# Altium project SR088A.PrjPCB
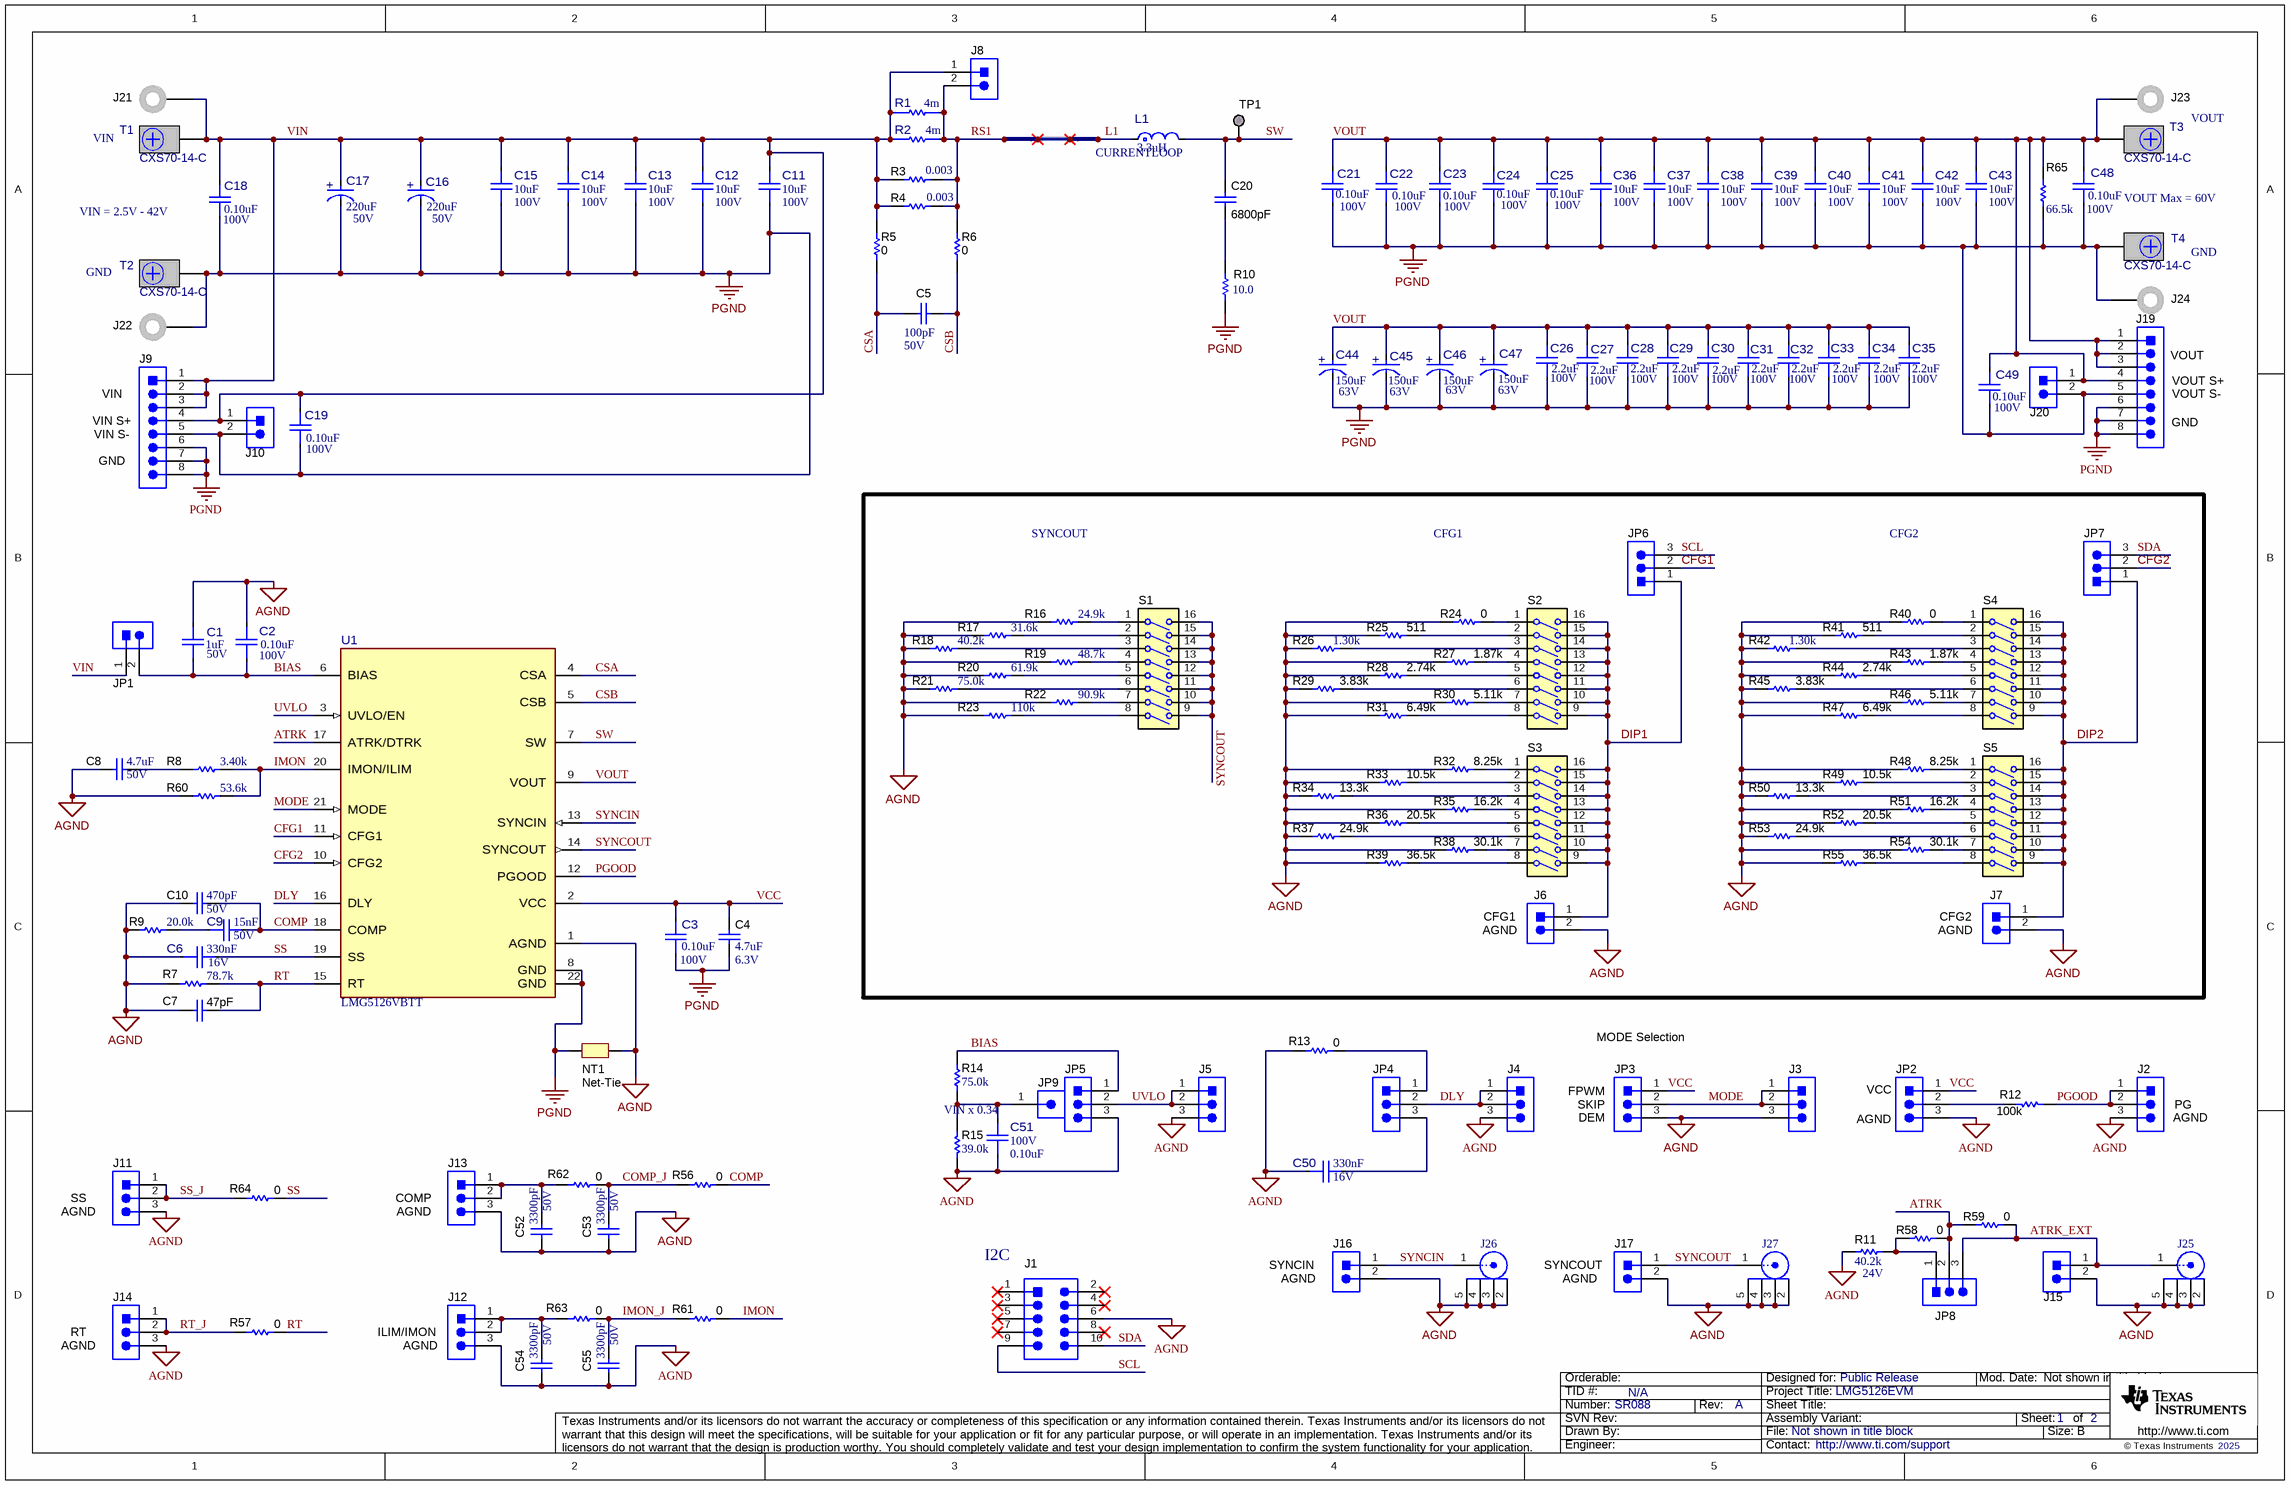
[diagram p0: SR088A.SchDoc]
TID: N/A; TechSupport: http://www.ti.com/support; SCH_Rev: A; PRJ_Title: LMG5126EVM; PRJ_Number: SR088; PRJ_Customer: Public Release; PCB_Rev: A; CopyrightYear: 2025
1 sheet, 168 parts. Net scope: global (net labels, ports and power ports of the same name join across sheets).
Board file: SR088A.PcbDoc

## Sheet SR088A.SchDoc
size 431 x 279 mm; Date: Not shown in title block; ApprovedBy: Not shown in title block; CheckedBy: Not shown in title block; Author: Not shown in title block; CompanyName: Not shown in title block; Engineer: Not shown in title block; Organization: Not shown in title block; Address1: Not shown in title block; Address2: Not shown in title block; Address3: Not shown in title block; Address4: Not shown in title block; DocumentNumber: 1; Revision: Use project parameter SCH_Rev; SheetNumber: 1; SheetTotal: 2; PageSetup: Record=PageOptions¦CenterHorizontal=True¦CenterVertical=True¦PrintScale=1.00¦XCorrection=1.00¦YCorrection=1.00¦PrintKind=0¦BorderSize=5000000¦LeftOffset=0¦BottomOffset=0¦Orientation=2¦PaperLength=1000¦PaperWidth=1000¦Scale=100¦PaperSource=15¦PrintQuality=600¦MediaType=1¦DitherType=10¦PaperKind=Letter¦PrintScaleMode=1

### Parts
C1  ValueDisplayed: 1uF  VDC_V: 50V  [FP-GCM188D71H105KE36J_0603-MFG]  (hidden comment: GCM188D71H105KE36J)
C2  VDC_V: 100V  ValueDisplayed: 0.10uF  [FP-GRM155R62A104ME14D_0402-S]  (hidden comment: GRM155R62A104ME14D)
C3  VDC_V: 100V  ValueDisplayed: 0.10uF  [FP-GRM155R62A104ME14D_0402-S]  (hidden comment: GRM155R62A104ME14D)
C4  VDC_V: 6.3V  ValueDisplayed: 4.7uF  [0402_065S]  (hidden comment: GRM155R60J475ME87D)
C5  VDC_V: 50V  ValueDisplayed: 100pF  [0402S]  (hidden comment: CGA2B2C0G1H101J050BA)
C6  Cap_F: 330nF  VDC_V: 16V  [FP-GRT188R71C334KE01D_0603-MFG]  (hidden comment: GRT188R71C334KE01D)
C7  ValueDisplayed: 47pF  [0603S]  (hidden comment: C0603C470J1GACAUTO)
C8  VDC_V: 50V  ValueDisplayed: 4.7uF  [1210_280]  (hidden comment: CGA6P3X7R1H475K250AB)
C9  Cap_F: 15nF  VDC_V: 50V  [FP-GCD188R71H153KA01D_0603-MFG]  (hidden comment: GCD188R71H153KA01D)
C10  VDC_V: 50V  ValueDisplayed: 470pF  [0402S]  (hidden comment: GRM1555C1H471JA01D)
C11  ValueDisplayed: 10uF  VDC_V: 100V  [FP-GRM32EC72A106KE05L_1210-MFG]  (hidden comment: GRM32EC72A106KE05L)
C12  ValueDisplayed: 10uF  VDC_V: 100V  [FP-GRM32EC72A106KE05L_1210-MFG]  (hidden comment: GRM32EC72A106KE05L)
C13  ValueDisplayed: 10uF  VDC_V: 100V  [FP-GRM32EC72A106KE05L_1210-MFG]  (hidden comment: GRM32EC72A106KE05L)
C14  ValueDisplayed: 10uF  VDC_V: 100V  [FP-GRM32EC72A106KE05L_1210-MFG]  (hidden comment: GRM32EC72A106KE05L)
C15  ValueDisplayed: 10uF  VDC_V: 100V  [FP-GRM32EC72A106KE05L_1210-MFG]  (hidden comment: GRM32EC72A106KE05L)
C16  ValueDisplayed: 220uF  VDC_V: 50V  [FP-EEHZU1H221P_RADIAL_SMT-MFG]  (hidden comment: EEHZU1H221P)
C17  ValueDisplayed: 220uF  VDC_V: 50V  [FP-EEHZU1H221P_RADIAL_SMT-MFG]  (hidden comment: EEHZU1H221P)
C18  VDC_V: 100V  ValueDisplayed: 0.10uF  [FP-GRM155R62A104ME14D_0402-S]  (hidden comment: GRM155R62A104ME14D)
C19  VDC_V: 100V  ValueDisplayed: 0.10uF  [FP-GRM155R62A104ME14D_0402-S]  (hidden comment: GRM155R62A104ME14D)
C20  ValueDisplayed: 6800pF  [0603S]  (hidden comment: GRM1885C1H682JA01D)
C21  VDC_V: 100V  ValueDisplayed: 0.10uF  [FP-GRM155R62A104ME14D_0402-S]  (hidden comment: GRM155R62A104ME14D)
C22  VDC_V: 100V  ValueDisplayed: 0.10uF  [FP-GRM155R62A104ME14D_0402-S]  (hidden comment: GRM155R62A104ME14D)
C23  VDC_V: 100V  ValueDisplayed: 0.10uF  [FP-GRM155R62A104ME14D_0402-S]  (hidden comment: GRM155R62A104ME14D)
C24  VDC_V: 100V  ValueDisplayed: 0.10uF  [FP-GRM155R62A104ME14D_0402-S]  (hidden comment: GRM155R62A104ME14D)
C25  VDC_V: 100V  ValueDisplayed: 0.10uF  [FP-GRM155R62A104ME14D_0402-S]  (hidden comment: GRM155R62A104ME14D)
C26  ValueDisplayed: 2.2uF  VDC_V: 100V  [FP-GRM21BD72A225ME01K_0805-MFG]  (hidden comment: GRM21BD72A225ME01K)
C27  ValueDisplayed: 2.2uF  VDC_V: 100V  [FP-GRM21BD72A225ME01K_0805-MFG]  (hidden comment: GRM21BD72A225ME01K)
C28  ValueDisplayed: 2.2uF  VDC_V: 100V  [FP-GRM21BD72A225ME01K_0805-MFG]  (hidden comment: GRM21BD72A225ME01K)
C29  ValueDisplayed: 2.2uF  VDC_V: 100V  [FP-GRM21BD72A225ME01K_0805-MFG]  (hidden comment: GRM21BD72A225ME01K)
C30  ValueDisplayed: 2.2uF  VDC_V: 100V  [FP-GRM21BD72A225ME01K_0805-MFG]  (hidden comment: GRM21BD72A225ME01K)
C31  ValueDisplayed: 2.2uF  VDC_V: 100V  [FP-GRM21BD72A225ME01K_0805-MFG]  (hidden comment: GRM21BD72A225ME01K)
C32  ValueDisplayed: 2.2uF  VDC_V: 100V  [FP-GRM21BD72A225ME01K_0805-MFG]  (hidden comment: GRM21BD72A225ME01K)
C33  ValueDisplayed: 2.2uF  VDC_V: 100V  [FP-GRM21BD72A225ME01K_0805-MFG]  (hidden comment: GRM21BD72A225ME01K)
C34  ValueDisplayed: 2.2uF  VDC_V: 100V  [FP-GRM21BD72A225ME01K_0805-MFG]  (hidden comment: GRM21BD72A225ME01K)
C35  ValueDisplayed: 2.2uF  VDC_V: 100V  [FP-GRM21BD72A225ME01K_0805-MFG]  (hidden comment: GRM21BD72A225ME01K)
C36  ValueDisplayed: 10uF  VDC_V: 100V  [FP-GRM32EC72A106KE05L_1210-MFG]  (hidden comment: GRM32EC72A106KE05L)
C37  ValueDisplayed: 10uF  VDC_V: 100V  [FP-GRM32EC72A106KE05L_1210-MFG]  (hidden comment: GRM32EC72A106KE05L)
C38  ValueDisplayed: 10uF  VDC_V: 100V  [FP-GRM32EC72A106KE05L_1210-MFG]  (hidden comment: GRM32EC72A106KE05L)
C39  ValueDisplayed: 10uF  VDC_V: 100V  [FP-GRM32EC72A106KE05L_1210-MFG]  (hidden comment: GRM32EC72A106KE05L)
C40  ValueDisplayed: 10uF  VDC_V: 100V  [FP-GRM32EC72A106KE05L_1210-MFG]  (hidden comment: GRM32EC72A106KE05L)
C41  ValueDisplayed: 10uF  VDC_V: 100V  [FP-GRM32EC72A106KE05L_1210-MFG]  (hidden comment: GRM32EC72A106KE05L)
C42  ValueDisplayed: 10uF  VDC_V: 100V  [FP-GRM32EC72A106KE05L_1210-MFG]  (hidden comment: GRM32EC72A106KE05L)
C43  ValueDisplayed: 10uF  VDC_V: 100V  [FP-GRM32EC72A106KE05L_1210-MFG]  (hidden comment: GRM32EC72A106KE05L)
C44  ValueDisplayed: 150uF  VDC_V: 63V  [FP-EEHZU1J151P_RADIAL_SMT-MFG]  (hidden comment: EEHZU1J151P)
C45  ValueDisplayed: 150uF  VDC_V: 63V  [FP-EEHZU1J151P_RADIAL_SMT-MFG]  (hidden comment: EEHZU1J151P)
C46  ValueDisplayed: 150uF  VDC_V: 63V  [FP-EEHZU1J151P_RADIAL_SMT-MFG]  (hidden comment: EEHZU1J151P)
C47  ValueDisplayed: 150uF  VDC_V: 63V  [FP-EEHZU1J151P_RADIAL_SMT-MFG]  (hidden comment: EEHZU1J151P)
C48  VDC_V: 100V  ValueDisplayed: 0.10uF  [FP-GRM155R62A104ME14D_0402-S]  (hidden comment: GRM155R62A104ME14D)
C49  VDC_V: 100V  ValueDisplayed: 0.10uF  [FP-GRM155R62A104ME14D_0402-S]  (hidden comment: GRM155R62A104ME14D)
C50  Cap_F: 330nF  VDC_V: 16V  [FP-GRT188R71C334KE01D_0603-MFG]  (hidden comment: GRT188R71C334KE01D)
C51  VDC_V: 100V  ValueDisplayed: 0.10uF  [FP-GRM155R62A104ME14D_0402-S]  (hidden comment: GRM155R62A104ME14D)
C52  VDC_V: 50V  ValueDisplayed: 3300pF  [0603S]  (hidden comment: GRM1885C1H332JA01D)
C53  VDC_V: 50V  ValueDisplayed: 3300pF  [0603S]  (hidden comment: GRM1885C1H332JA01D)
C54  VDC_V: 50V  ValueDisplayed: 3300pF  [0603S]  (hidden comment: GRM1885C1H332JA01D)
C55  VDC_V: 50V  ValueDisplayed: 3300pF  [0603S]  (hidden comment: GRM1885C1H332JA01D)
J1  Header_5x2  [CONN_2510-6002]  (value not drawn)
J2  61300311121  [WURTH_61300311121]  (value not drawn)
J3  61300311121  [WURTH_61300311121]  (value not drawn)
J4  61300311121  [WURTH_61300311121]  (value not drawn)
J5  61300311121  [WURTH_61300311121]  (value not drawn)
J6  61300211121  [WURTH_61300211121]  (value not drawn)
J7  61300211121  [WURTH_61300211121]  (value not drawn)
J8  61300211121  [WURTH_61300211121]  (value not drawn)
J9  PEC08SAAN  [SULLINS_PEC08SAAN]  (value not drawn)
J10  61300211121  [WURTH_61300211121]  (value not drawn)
J11  61300311121  [WURTH_61300311121]  (value not drawn)
J12  61300311121  [WURTH_61300311121]  (value not drawn)
J13  61300311121  [WURTH_61300311121]  (value not drawn)
J14  61300311121  [WURTH_61300311121]  (value not drawn)
J15  61300211121  [WURTH_61300211121]  (value not drawn)
J16  61300211121  [WURTH_61300211121]  (value not drawn)
J17  61300211121  [WURTH_61300211121]  (value not drawn)
J19  PEC08SAAN  [SULLINS_PEC08SAAN]  (value not drawn)
J20  61300211121  [WURTH_61300211121]  (value not drawn)
J21  108-0740-001  [Johnson_108-0740-001]  (value not drawn)
J22  108-0740-001  [Johnson_108-0740-001]  (value not drawn)
J23  108-0740-001  [Johnson_108-0740-001]  (value not drawn)
J24  108-0740-001  [Johnson_108-0740-001]  (value not drawn)
J25  MMCX-J-P-H-ST-TH1  [Samtec_MMCX-J-P-H-ST-TH1]  (value not drawn)
J26  MMCX-J-P-H-ST-TH1  [Samtec_MMCX-J-P-H-ST-TH1]  (value not drawn)
J27  MMCX-J-P-H-ST-TH1  [Samtec_MMCX-J-P-H-ST-TH1]  (value not drawn)
JP1  61300211121  [WURTH_61300211121]  (value not drawn)
JP2  61300311121  [WURTH_61300311121]  (value not drawn)
JP3  61300311121  [WURTH_61300311121]  (value not drawn)
JP4  61300311121  [WURTH_61300311121]  (value not drawn)
JP5  61300311121  [WURTH_61300311121]  (value not drawn)
JP6  61300311121  [WURTH_61300311121]  (value not drawn)
JP7  61300311121  [WURTH_61300311121]  (value not drawn)
JP8  61300311121  [WURTH_61300311121]  (value not drawn)
JP9  61300111121  [WURTH_61300111121]  (value not drawn)
L1  value 3.3uH  [FP-XGL1712-332MED_SMT2_17MM2_18MM2-MFG]  (hidden comment: XGL1712-332MED)
NT1  Net-Tie  [Net-Tie_6x8mil]  (net tie, no BOM)
R1  value 4m  [FP-KRL2012E-M-R004-F-T5_2012-MFG]  (hidden comment: KRL2012E-M-R004-F-T5)
R2  value 4m  [FP-KRL2012E-M-R004-F-T5_2012-MFG]  (hidden comment: KRL2012E-M-R004-F-T5)
R3  ValueDisplayed: 0.003  [2512_WIDE]  (hidden comment: KRL6432E-M-R003-F-T1)
R4  ValueDisplayed: 0.003  [2512_WIDE]  (hidden comment: KRL6432E-M-R003-F-T1)
R5  ValueDisplayed: 0  [0603S]  (hidden comment: ERJ-3GEY0R00V)
R6  ValueDisplayed: 0  [0603S]  (hidden comment: ERJ-3GEY0R00V)
R7  ValueDisplayed: 78.7k  [0603S]  (hidden comment: CRCW060378K7FKEA)
R8  ValueDisplayed: 3.40k  [0603S]  (hidden comment: CRCW06033K40FKEA)
R9  ValueDisplayed: 20.0k  [0603S]  (hidden comment: CRCW060320K0FKEA)
R10  ValueDisplayed: 10.0  [1218]  (hidden comment: CRCW121810R0FKEK)
R11  ValueDisplayed: 40.2k  [0603S]  (hidden comment: CRCW060340K2FKEA)
R12  ValueDisplayed: 100k  [0603S]  (hidden comment: CRCW0603100KFKEA)
R13  ValueDisplayed: 0  [0603S]  (hidden comment: RMCF0603ZT0R00)
R14  ValueDisplayed: 75.0k  [0603S]  (hidden comment: CRCW060375K0FKEA)
R15  ValueDisplayed: 39.0k  [0603S]  (hidden comment: RC0603FR-0739KL)
R16  ValueDisplayed: 24.9k  [0603S]  (hidden comment: CRCW060324K9FKEA)
R17  ValueDisplayed: 31.6k  [0603S]  (hidden comment: CRCW060331K6FKEA)
R18  ValueDisplayed: 40.2k  [0603S]  (hidden comment: CRCW060340K2FKEA)
R19  ValueDisplayed: 48.7k  [0603S]  (hidden comment: CRCW060348K7FKEA)
R20  ValueDisplayed: 61.9k  [0603S]  (hidden comment: CRCW060361K9FKEA)
R21  ValueDisplayed: 75.0k  [0603S]  (hidden comment: CRCW060375K0FKEA)
R22  ValueDisplayed: 90.9k  [0603S]  (hidden comment: CRCW060390K9FKEA)
R23  ValueDisplayed: 110k  [0603S]  (hidden comment: CRCW0603110KFKEA)
R24  ValueDisplayed: 0  [0603S]  (hidden comment: RMCF0603ZT0R00)
R25  ValueDisplayed: 511  [0603S]  (hidden comment: CRCW0603511RFKEA)
R26  ValueDisplayed: 1.30k  [0603S]  (hidden comment: CRCW06031K30FKEA)
R27  ValueDisplayed: 1.87k  [0603S]  (hidden comment: CRCW06031K87FKEA)
R28  ValueDisplayed: 2.74k  [0603S]  (hidden comment: CRCW06032K74FKEA)
R29  ValueDisplayed: 3.83k  [0603S]  (hidden comment: CRCW06033K83FKEA)
R30  ValueDisplayed: 5.11k  [0603S]  (hidden comment: CRCW06035K11FKEA)
R31  ValueDisplayed: 6.49k  [0603S]  (hidden comment: CRCW06036K49FKEA)
R32  ValueDisplayed: 8.25k  [0603S]  (hidden comment: CRCW06038K25FKEA)
R33  ValueDisplayed: 10.5k  [0603S]  (hidden comment: CRCW060310K5FKEA)
R34  ValueDisplayed: 13.3k  [0603S]  (hidden comment: CRCW060313K3FKEA)
R35  ValueDisplayed: 16.2k  [0603S]  (hidden comment: CRCW060316K2FKEA)
R36  ValueDisplayed: 20.5k  [0603S]  (hidden comment: CRCW060320K5FKEA)
R37  ValueDisplayed: 24.9k  [0603S]  (hidden comment: CRCW060324K9FKEA)
R38  ValueDisplayed: 30.1k  [0603S]  (hidden comment: CRCW060330K1FKEA)
R39  ValueDisplayed: 36.5k  [0603S]  (hidden comment: CRCW060336K5FKEA)
R40  ValueDisplayed: 0  [0603S]  (hidden comment: RMCF0603ZT0R00)
R41  ValueDisplayed: 511  [0603S]  (hidden comment: CRCW0603511RFKEA)
R42  ValueDisplayed: 1.30k  [0603S]  (hidden comment: CRCW06031K30FKEA)
R43  ValueDisplayed: 1.87k  [0603S]  (hidden comment: CRCW06031K87FKEA)
R44  ValueDisplayed: 2.74k  [0603S]  (hidden comment: CRCW06032K74FKEA)
R45  ValueDisplayed: 3.83k  [0603S]  (hidden comment: CRCW06033K83FKEA)
R46  ValueDisplayed: 5.11k  [0603S]  (hidden comment: CRCW06035K11FKEA)
R47  ValueDisplayed: 6.49k  [0603S]  (hidden comment: CRCW06036K49FKEA)
R48  ValueDisplayed: 8.25k  [0603S]  (hidden comment: CRCW06038K25FKEA)
R49  ValueDisplayed: 10.5k  [0603S]  (hidden comment: CRCW060310K5FKEA)
R50  ValueDisplayed: 13.3k  [0603S]  (hidden comment: CRCW060313K3FKEA)
R51  ValueDisplayed: 16.2k  [0603S]  (hidden comment: CRCW060316K2FKEA)
R52  ValueDisplayed: 20.5k  [0603S]  (hidden comment: CRCW060320K5FKEA)
R53  ValueDisplayed: 24.9k  [0603S]  (hidden comment: CRCW060324K9FKEA)
R54  ValueDisplayed: 30.1k  [0603S]  (hidden comment: CRCW060330K1FKEA)
R55  ValueDisplayed: 36.5k  [0603S]  (hidden comment: CRCW060336K5FKEA)
R56  ValueDisplayed: 0  [0603S]  (hidden comment: RMCF0603ZT0R00)
R57  ValueDisplayed: 0  [0603S]  (hidden comment: RMCF0603ZT0R00)
R58  ValueDisplayed: 0  [0603S]  (hidden comment: RMCF0603ZT0R00)
R59  ValueDisplayed: 0  [0603S]  (hidden comment: RMCF0603ZT0R00)
R60  ValueDisplayed: 53.6k  [0603S]  (hidden comment: CRCW060353K6FKEA)
R61  ValueDisplayed: 0  [0603S]  (hidden comment: RMCF0603ZT0R00)
R62  ValueDisplayed: 0  [0603S]  (hidden comment: ERJ-3GEY0R00V)
R63  ValueDisplayed: 0  [0603S]  (hidden comment: ERJ-3GEY0R00V)
R64  ValueDisplayed: 0  [0603S]  (hidden comment: RMCF0603ZT0R00)
R65  ValueDisplayed: 66.5k  [0603S]  (hidden comment: CRCW060366K5FKEA)
S1  218-8LPST  [SW_218-8LP]  (value not drawn)
S2  218-8LPST  [SW_218-8LP]  (value not drawn)
S3  218-8LPST  [SW_218-8LP]  (value not drawn)
S4  218-8LPST  [SW_218-8LP]  (value not drawn)
S5  218-8LPST  [SW_218-8LP]  (value not drawn)
T1  CXS70-14-C  [Panduit_CXS70-14-C]
T2  CXS70-14-C  [Panduit_CXS70-14-C]
T3  CXS70-14-C  [Panduit_CXS70-14-C]
T4  CXS70-14-C  [Panduit_CXS70-14-C]
TP1  RCU-0C  [TE_RCU]  (value not drawn)
U1  LMG5126VBTT  [VBT0022A-MFG]

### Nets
AGND: C1.2 C2.2 C6.1 C7.1 C8.2 C10.2 C50.1 C51.1 C52.2 C53.2 C54.2 C55.2 J1.6 J2.3 J3.3 J4.3 J5.3 J6.2 J7.2 J11.3 J12.3 J13.3 J14.3 J15.2 J16.2 J17.2 J25.2 J25.3 J25.4 J25.5 J26.2 J26.3 J26.4 J26.5 J27.2 J27.3 J27.4 J27.5 JP2.3 JP3.3 JP5.3 NT1.2 R7.1 R9.1 R11.1 R13.2 R15.2 R16.1 R17.1 R18.1 R19.2 R20.1 R21.1 R22.1 R23.2 R24.2 R25.1 R26.2 R27.1 R28.2 R29.1 R30.1 R31.1 R32.1 R33.1 R34.1 R35.2 R36.1 R37.1 R38.1 R39.2 R40.2 R41.1 R42.2 R43.1 R44.2 R45.1 R46.1 R47.1 R48.1 R49.1 R50.1 R51.2 R52.1 R53.1 R54.1 R55.2 R60.1 U1.1(AGND)
PGND: C3.1 C4.2 C11.1 C12.1 C13.1 C14.1 C15.1 C16.1(CATHODE) C17.1(CATHODE) C18.1 C19.1 C21.1 C22.1 C23.1 C24.1 C25.1 C26.1 C27.1 C28.1 C29.1 C30.1 C31.1 C32.1 C33.1 C34.1 C35.1 C36.1 C37.1 C38.1 C39.1 C40.1 C41.1 C42.1 C43.1 C44.1(CATHODE) C45.1(CATHODE) C46.1(CATHODE) C47.1(CATHODE) C48.1 C49.1 J9.5 J9.6 J9.7 J9.8 J10.2 J19.5 J19.6 J19.7 J19.8 J20.2 J22.1 J24.1 NT1.1 R10.1 R65.1 T2.1 T4.1 U1.8(GND) U1.22(GND)
ATRK: JP8.2 R58.1 R59.2 U1.17(ATRK/DTRK)
ATRK_EXT: J15.1 J25.1 JP8.3 R59.1
BIAS: C1.1 C2.1 JP1.2 JP5.1 R14.2 U1.6(BIAS)
CFG1: JP6.2 U1.11(CFG1)
CFG2: JP7.2 U1.10(CFG2)
COMP: C9.2 C10.1 R56.1 U1.18(COMP)
COMP_J: C53.1 R56.2 R62.1
CSA: C5.2 R5.1 U1.4(CSA)
CSB: C5.1 R6.1 U1.5(CSB)
DIP1: J6.1 JP6.1 S2.9(8A) S2.10(7A) S2.11(6A) S2.12(5A) S2.13(4A) S2.14(3A) S2.15(2A) S2.16(1A) S3.9(8A) S3.10(7A) S3.11(6A) S3.12(5A) S3.13(4A) S3.14(3A) S3.15(2A) S3.16(1A)
DIP2: J7.1 JP7.1 S4.9(8A) S4.10(7A) S4.11(6A) S4.12(5A) S4.13(4A) S4.14(3A) S4.15(2A) S4.16(1A) S5.9(8A) S5.10(7A) S5.11(6A) S5.12(5A) S5.13(4A) S5.14(3A) S5.15(2A) S5.16(1A)
DLY: J4.1 J4.2 JP4.2 U1.16(DLY)
IMON: R8.2 R60.2 R61.1 U1.20(IMON/ILIM)
IMON_J: C55.1 R61.2 R63.1
L1: J8.2 L1.1 R1.2 R2.2 R3.2 R4.2 R6.2  [also labelled RS1]
MODE: J3.1 J3.2 JP3.2 U1.21(MODE)
PGOOD: J2.1 J2.2 R12.2 U1.12(PGOOD)
RT: C7.2 R7.2 R57.1 U1.15(RT)
RT_J: J14.1 J14.2 R57.2
SCL: J1.9 JP6.3
SDA: J1.10 JP7.3
SS: C6.2 R64.1 U1.19(SS)
SS_J: J11.1 J11.2 R64.2
SW: C20.1 L1.2 TP1.1 U1.7(SW)
SYNCIN: J16.1 J26.1 U1.13(SYNCIN)
SYNCOUT: J17.1 J27.1 S1.9(8A) S1.10(7A) S1.11(6A) S1.12(5A) S1.13(4A) S1.14(3A) S1.15(2A) S1.16(1A) U1.14(SYNCOUT)
UVLO: J5.1 J5.2 JP5.2 U1.3(UVLO/EN)
VCC: C3.2 C4.1 JP2.1 JP3.1 U1.2(VCC)
VIN: C11.2 C12.2 C13.2 C14.2 C15.2 C16.2(ANODE) C17.2(ANODE) C18.2 C19.2 J8.1 J9.1 J9.2 J9.3 J9.4 J10.1 J21.1 JP1.1 R1.1 R2.1 R3.1 R4.1 R5.2 T1.1
VOUT: C21.2 C22.2 C23.2 C24.2 C25.2 C26.2 C27.2 C28.2 C29.2 C30.2 C31.2 C32.2 C33.2 C34.2 C35.2 C36.2 C37.2 C38.2 C39.2 C40.2 C41.2 C42.2 C43.2 C44.2(ANODE) C45.2(ANODE) C46.2(ANODE) C47.2(ANODE) C48.2 C49.2 J19.1 J19.2 J19.3 J19.4 J20.1 J23.1 R65.2 T3.1 U1.9(VOUT)
NetC8_1: C8.1 R8.1
NetC9_1: C9.1 R9.2
NetC20_2: C20.2 R10.2
NetC50_2: C50.2 JP4.3
NetC51_2: C51.2 JP9.1 R14.1 R15.1
NetC52_1: C52.1 J13.1 J13.2 R62.2
NetC54_1: C54.1 J12.1 J12.2 R63.2
NetJP2_2: JP2.2 R12.1
NetJP4_1: JP4.1 R13.1
NetJP8_1: JP8.1 R11.2 R58.2
NetR16_2: R16.2 S1.1
NetR17_2: R17.2 S1.2
NetR18_2: R18.2 S1.3
NetR19_1: R19.1 S1.4
NetR20_2: R20.2 S1.5
NetR21_2: R21.2 S1.6
NetR22_2: R22.2 S1.7
NetR23_1: R23.1 S1.8
NetR24_1: R24.1 S2.1
NetR25_2: R25.2 S2.2
NetR26_1: R26.1 S2.3
NetR27_2: R27.2 S2.4
NetR28_1: R28.1 S2.5
NetR29_2: R29.2 S2.6
NetR30_2: R30.2 S2.7
NetR31_2: R31.2 S2.8
NetR32_2: R32.2 S3.1
NetR33_2: R33.2 S3.2
NetR34_2: R34.2 S3.3
NetR35_1: R35.1 S3.4
NetR36_2: R36.2 S3.5
NetR37_2: R37.2 S3.6
NetR38_2: R38.2 S3.7
NetR39_1: R39.1 S3.8
NetR40_1: R40.1 S4.1
NetR41_2: R41.2 S4.2
NetR42_1: R42.1 S4.3
NetR43_2: R43.2 S4.4
NetR44_1: R44.1 S4.5
NetR45_2: R45.2 S4.6
NetR46_2: R46.2 S4.7
NetR47_2: R47.2 S4.8
NetR48_2: R48.2 S5.1
NetR49_2: R49.2 S5.2
NetR50_2: R50.2 S5.3
NetR51_1: R51.1 S5.4
NetR52_2: R52.2 S5.5
NetR53_2: R53.2 S5.6
NetR54_2: R54.2 S5.7
NetR55_1: R55.1 S5.8

Not connected (* = marked no-connect by the designer): J1 1* 2* 3* 4* 5* 7* 8*

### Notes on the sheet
- VIN
- (near L1) CURRENTLOOP
- VOUT
- VIN = 2.5V - 42V
- VOUT Max = 60V
- GND
- (near J9) VIN S+
- (near J9) VIN S-
- (near J9) VIN
- (near J19) GND
- (near J19) VOUT S-
- (near J19) VOUT S+
- (near J9) GND
- SYNCOUT
- CFG1
- CFG2
- AGND
- (near JP3) MODE Selection
- (near JP3) FPWM
- (near JP3) SKIP
- (near JP2) VCC
- (near J2) PG
- VIN x 0.34
- (near JP3) DEM
- (near JP2) AGND
- (near J2) AGND
- SS
- (near J11) AGND
- (near J13) COMP
- (near J13) AGND
- (near J1) I2C
- (near J16) SYNCIN
- (near J16) AGND
- (near R11) 24V
- RT
- (near J14) AGND
- (near J12) ILIM/IMON
- (near J12) AGND

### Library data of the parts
C1 = CMP-0122291-1: 1 µF ±10% 50V Ceramic Capacitor X7T 0603 (1608 Metric); Manufacturer: Murata; AEC Qualified: No; Cap_F: 1µF; SizeZ_mm: 1mm; TempCo: +22/-33%; Value: 1µF
C2 C3 C18 C19 C21-C25 C48 C49 C51 = CMP-0093748-2: Chip Multilayer Ceramic Capacitors for General Purpose, 0402, 0.10uF, X5R, 15%, 20%, 100V; Manufacturer: Murata; AEC Qualified: No; Cap_F: 100nF; SizeZ_mm: 0.55mm; Value: 100nF
C4 = CMP-0006553-3: CAP, CERM, 4.7 uF, 6.3 V, +/- 20%, X5R, 0402; Manufacturer: MuRata; TaMin_C: -55°C; ESR_ohm: 9m; Polarized: N; SizeAreaWB_mm2: 3; Value1: 0.009 ohm; U/M: EA; Value: 4.7uF; TaMax_C: 85°C; SizeZ_mm: 0.6; SizeX_mm: 1; SizeY_mm: 0.5; Cap_Case: 0402; Cap_F: 4.7µF; IRMS_A: 1.22A; AEC Category: Q200; Green_Lifecycle: Active; Green_REACh: Incomplete
C5 = CMP-0006308-2: CAP, CERM, 100 pF, 50 V, +/- 5%, C0G/NP0, AEC-Q200 Grade 1, 0402; Manufacturer: TDK; TaMin_C: -55°C; Polarized: N; SizeAreaWB_mm2: 3; Value1: Unknown; U/M: EA; Value: 100pF; TaMax_C: 125°C; SizeZ_mm: 0.6; SizeX_mm: 1; SizeY_mm: 0.5; Cap_Case: 0402; AEC Qualified: Y; AEC Category: Q200
C6 C50 = CMP-0121474-1: Multi-Layer Ceramic Capacitor 330nF 16V X7R ±10% 0603 Paper T/R; Manufacturer: Murata; AEC Grade: Grade 1; AEC Qualified: Yes; SizeZ_mm: 0.9mm; TempCo: 15%
C7 = CMP-0085572-1: CAP, CERM, 47 pF, 100 V,+/- 5%, C0G/NP0, AEC-Q200 Grade 1, 0603; Manufacturer: Kemet; TaMax_C: 125°C; AEC Category: Q200; AEC Grade: 1; VDC_V: 100V; TaMin_C: -55°C; SizeArea_mm2: 1.28; Value: 47pF; AEC Qualified: Y; Polarized: N; SizeX_mm: 1.6; U/M: EA; SizeY_mm: 0.8; Cap_Case: 0603; SizeAreaWB_mm2: 4.68
C8 = CMP-0009162-2: CAP, CERM, 4.7 uF, 50 V, +/- 10%, X7R, AEC-Q200 Grade 1, 1210; Manufacturer: TDK; TaMin_C: -55°C; ESR_ohm: 3.166m; Polarized: N; SizeAreaWB_mm2: 14.7; Value1: 0.003166 ohm; U/M: EA; Value: 4.7uF; TaMax_C: 125°C; SizeZ_mm: 2.8; SizeX_mm: 3.2; SizeY_mm: 2.5; SizeArea_mm2: 8; AEC Qualified: Y; Cap_F: 4.7µF; IRMS_A: 4.1331A; AEC Grade: 1; AEC Category: Q200
C9 = CMP-0121472-1: Chip Multilayer Ceramic Capacitors for Automotive, 0603, 15000pF, X7R, 15%, 10%, 50V, Grade 1; Manufacturer: Murata; AEC Grade: Grade 1; AEC Qualified: Yes; SizeZ_mm: 0.9mm; Value: 15nF
C10 = CMP-0006470-2: CAP, CERM, 470 pF, 50 V, +/- 5%, C0G/NP0, 0402; Manufacturer: MuRata; TaMin_C: -55°C; Polarized: N; SizeAreaWB_mm2: 3; Value1: Unknown; U/M: EA; Value: 470pF; TaMax_C: 125°C; SizeZ_mm: 0.6; SizeX_mm: 1; SizeY_mm: 0.5; Cap_Case: 0402; AEC Category: Q200
C11-C15 C36-C43 = CMP-0087970-1: 10µF ±10% 100V Ceramic Capacitor X7S 1210 (3225 Metric); Manufacturer: Murata; Symbol Name: SYM-GRM32EC72A106KE05L; AEC Qualified: No; TempCo: 22%; SizeZ_mm: 2.7mm
C16 C17 = CMP-0120360-1: Aluminum Hybrid Polymer Capacitors 220uF 20% 50V Life 4000Hours AEC-Q200 RADIAL SMT; Manufacturer: Panasonic; AEC Grade: Grade 1; AEC Qualified: Yes; Cap_F: 220µF; IRMS_A: 5.2A; SizeZ_mm: 16.8mm; Dissipation Factor: 10%; Esr: 10mΩ; Leakage Current: 110uA; Value: 220µF
C20 = CMP-0078296-1: CAP, CERM, 6800 pF, 50 V,+/- 5%, C0G/NP0, 0603; Manufacturer: MuRata; TaMin_C: -55°C; Polarized: N; SizeAreaWB_mm2: 4.68; U/M: EA; Value: 6800pF; TaMax_C: 125°C; SizeZ_mm: 1; SizeX_mm: 1.6; SizeY_mm: 0.8; Cap_Case: 0603; Value2: 50V; SizeArea_mm2: 1.28; Cap_F: 6.8nF; AEC Category: Q200
C26-C35 = CMP-0096278-1: Chip Multilayer Ceramic Capacitor for General Purpose 2.2uF ±20% 100V X7T SMD 0805; Manufacturer: Murata; AEC Qualified: No; Cap_F: 2.2µF; Value: 2.2µF; SizeZ_mm: 1.45mm; TempCo: +22/-33%
C44-C47 = CMP-0120392-1: Aluminum Hybrid Polymer Capacitors 150uF 20% 63V Life 4000Hours AEC-Q200 RADIAL SMT; Manufacturer: Panasonic; AEC Grade: Grade 1; AEC Qualified: Yes; Cap_F: 150µF; IRMS_A: 5.2A; SizeZ_mm: 16.8mm; Dissipation Factor: 8%; Esr: 10mΩ; Leakage Current: 94.5uA; Value: 150µF
C52-C55 = CMP-0007210-4: CAP, CERM, 3300 pF, 50 V, +/- 5%, C0G/NP0, 0603; Manufacturer: MuRata; TaMin_C: -55°C; Polarized: N; SizeAreaWB_mm2: 4.68; Value1: Unknown; U/M: EA; Value: 3300pF; TaMax_C: 125°C; SizeZ_mm: 1; SizeX_mm: 1.6; SizeY_mm: 0.8; Cap_Case: 0603; SizeArea_mm2: 1.28; Cap_F: 3.3nF; AEC Category: Q200
J1 = CMP-0055448-2: Header (shrouded), 100mil, 5x2, High-Temperature, Gold, TH; PartNumber: N2510-6002-RB; Manufacturer: 3M; Green_Lifecycle: Active; Green_REACh: Passed
J2-J5 J11-J14 JP2-JP5 JP8 = CMP-0054796-4: Header, 2.54 mm, 3x1, Gold, TH; Manufacturer: Wurth Elektronik; Green_Lifecycle: Active; Green_REACh: Passed; CT: FALSE; CNHeader: TRUE
J6 J7 J17 = CMP-0054794-2: Header, 2.54 mm, 2x1, Gold, TH; Manufacturer: Wurth Elektronik; Pitch_mm: 2.54; Gender: Male; Cert_UL: Y; Green_REACh: Passed; Shrouded: N; Green_Lifecycle: Active; Row_Count: 1
J8 J10 J15 J16 J20 = CMP-0054794-2: Header, 2.54 mm, 2x1, Gold, TH; Manufacturer: Wurth Elektronik; Green_Lifecycle: Active; Green_REACh: Passed; Cert_UL: Y; Gender: Male; Pitch_mm: 2.54; Row_Count: 1; Shrouded: N
J9 J19 = CMP-0054563-1: Header, 100mil, 8x1, Tin, TH; Manufacturer: Sullins Connector Solutions; CNHeader: TRUE; Current_A: 3A; Green_Lifecycle: Not Set; Shrouded: N; Gender: Male; Green_REACh: Incomplete; Voltage_V: 1.8kV; Row_Count: 1; Pitch_mm: 2.54; CT: FALSE; Cert_UL: Y
J21-J24 = CMP-0055387-2: Standard Banana Jack, Uninsulated, 15A; Manufacturer: Cinch Connectivity; CNHeader: FALSE; Green_Lifecycle: Active; Green_REACh: Passed; CT: TRUE
J25-J27 = CMP-0075554-1: Connector, MMCX 50 ohm, TH; Manufacturer: Samtec; CT: False; Gender: Female
JP1 = CMP-0054794-2: Header, 2.54 mm, 2x1, Gold, TH; Manufacturer: Wurth Elektronik; Shrouded: N; Gender: Male; Green_REACh: Passed; Pitch_mm: 2.54; Green_Lifecycle: Active; Row_Count: 1; Cert_UL: Y
JP6 JP7 = CMP-0054796-4: Header, 2.54 mm, 3x1, Gold, TH; Manufacturer: Wurth Elektronik; Green_REACh: Passed; Green_Lifecycle: Active; CT: FALSE; CNHeader: TRUE
JP9 = CMP-0054792-1: Header, 2.54 mm, 1x1, Gold, TH; Manufacturer: Wurth Elektronik; CNHeader: TRUE; CT: FALSE
L1 = CMP-0120649-1: Shielded Power Inductors 3.3µH ±20% 41.7A 1.9mOhms; Manufacturer: Coilcraft; AEC Grade: Grade 1; AEC Qualified: Yes; DCR_ohm: 1.9m; Isat: 23A; Material: Composite; SizeZ_mm: 12mm; Self Resonant Frequency: 15MHz; Shrouded: true; TaMax_C: +125°C; TaMin_C: -40°C; Test Frequency: 100kHz
NT1 = CMP-0078142-6: Single point connection between nets.
R1 R2 = CMP-0090660-1: 4 mOhms ±1% 1W Chip Resistor Wide 0805 (2012 Metric), 0508 Automotive AEC-Q200, Current Sense Metal Foil; Manufacturer: Susumu; AEC Grade: Grade 0; TempCo: 50ppm/°C; SizeZ_mm: 0.7mm; AEC Qualified: Yes
R3 R4 = CMP-0015106-2: RES, 0.003, 1%, 3 W, AEC-Q200 Grade 0, 2512 WIDE; Manufacturer: Susumu Co Ltd; Power_W: 3W; TempCo: 50 ppm/C; SizeAreaWB_mm2: 43.16; Value_Code: 3L000; U/M: EA; Value: 0.003; EIA_Code: E96; Res_ohm: 3m; SizeX_mm: 3.2; SizeY_mm: 6.3; SizeZ_mm: 0.7; SizeArea_mm2: 20.16; AEC Qualified: Y; AEC Grade: 0; AEC Category: Q200
R5 R6 R62 R63 = CMP-0025874-4: RES, 0, 5%, 0.1 W, AEC-Q200 Grade 0, 0603; Manufacturer: Panasonic; Power_W: 100mW; TempCo: 600 ppm/C; Value_Code: 0000; Value: 0; EIA_Code: E24; SizeX_mm: 1.6; SizeY_mm: 0.8; SizeZ_mm: 1; Value2: 0.1W; SizeArea_mm2: 1.28; AEC Qualified: Y; VDC_V: 50V; AEC Category: Q200; SizeAreaWB_mm2: 4.68
R7 = CMP-0022597-4: RES, 78.7 k, 1%, 0.1 W, AEC-Q200 Grade 0, 0603; Manufacturer: Vishay-Dale; Power_W: 100mW; TempCo: 100 ppm/C; Value_Code: 78k7; Value: 78.7k; EIA_Code: E96; SizeX_mm: 1.6; SizeY_mm: 0.8; SizeZ_mm: 1; Value2: 0.1W; SizeArea_mm2: 1.28; AEC Qualified: Y; VDC_V: 75V; AEC Category: Q200; AEC Grade: 0
R8 = CMP-0022376-4: RES, 3.40 k, 1%, 0.1 W, AEC-Q200 Grade 0, 0603; Manufacturer: Vishay-Dale; Power_W: 100mW; TempCo: 100 ppm/C; Value_Code: 3k40; Value: 3.40k; EIA_Code: E96; Res_ohm: 3.4k; SizeX_mm: 1.6; SizeY_mm: 0.8; SizeZ_mm: 1; Value2: 0.1W; SizeArea_mm2: 1.28; AEC Qualified: Y; VDC_V: 75V; AEC Category: Q200; AEC Grade: 0
R9 = CMP-0022204-4: RES, 20.0 k, 1%, 0.1 W, AEC-Q200 Grade 0, 0603; Manufacturer: Vishay-Dale; Power_W: 100mW; TempCo: 100 ppm/C; Value_Code: 20k0; Value: 20.0k; EIA_Code: E96; Res_ohm: 20k; SizeX_mm: 1.6; SizeY_mm: 0.8; SizeZ_mm: 1; Value2: 0.1W; SizeArea_mm2: 1.28; AEC Qualified: Y; VDC_V: 75V; AEC Category: Q200; AEC Grade: 0
R10 = CMP-0015024-3: RES, 10.0, 1%, 1 W, AEC-Q200 Grade 0, 1218; Manufacturer: Vishay-Dale; Power_W: 1W; TempCo: 100 ppm/C; SizeAreaWB_mm2: 23.52; Value_Code: 10R0; Value: 10.0; EIA_Code: E96; Res_ohm: 10; SizeX_mm: 3.2; SizeY_mm: 4.6; SizeZ_mm: 0.6; SizeArea_mm2: 14.72; AEC Qualified: Y; VDC_V: 200V; AEC Category: Q200; AEC Grade: 0
R11 R18 = CMP-0022410-4: RES, 40.2 k, 1%, 0.1 W, AEC-Q200 Grade 0, 0603; Manufacturer: Vishay-Dale; Power_W: 100mW; TempCo: 100 ppm/C; Value_Code: 40k2; Value: 40.2k; EIA_Code: E96; SizeX_mm: 1.6; SizeY_mm: 0.8; SizeZ_mm: 1; Value2: 0.1W; SizeArea_mm2: 1.28; AEC Qualified: Y; VDC_V: 75V; AEC Category: Q200; AEC Grade: 0
R12 = CMP-0021990-4: RES, 100 k, 1%, 0.1 W, AEC-Q200 Grade 0, 0603; Manufacturer: Vishay-Dale; Power_W: 100mW; TempCo: 100 ppm/C; Value: 100k; EIA_Code: E96; SizeX_mm: 1.6; SizeY_mm: 0.8; SizeZ_mm: 1; Value2: 0.1W; SizeArea_mm2: 1.28; AEC Qualified: Y; VDC_V: 75V; AEC Category: Q200; AEC Grade: 0
R13 R24 R40 R56-R59 R61 R64 = CMP-0023343-3: RES, 0, 1%, 0.1 W, AEC-Q200 Grade 0, 0603; Manufacturer: Stackpole Electronics Inc; Power_W: 100mW; TempCo: ppm/C; U/M: EA; Value: 0; SizeX_mm: 1.6; SizeY_mm: 0.8; SizeZ_mm: 1; Value2: 0.1W; SizeArea_mm2: 1.28; AEC Qualified: Y; AEC Category: Q200
R14 R21 = CMP-0022589-4: RES, 75.0 k, 1%, 0.1 W, AEC-Q200 Grade 0, 0603; Manufacturer: Vishay-Dale; Power_W: 100mW; TempCo: 100 ppm/C; Value_Code: 75k0; Value: 75.0k; EIA_Code: E96; Res_ohm: 75k; SizeX_mm: 1.6; SizeY_mm: 0.8; SizeZ_mm: 1; Value2: 0.1W; SizeArea_mm2: 1.28; AEC Qualified: Y; VDC_V: 75V; AEC Category: Q200; AEC Grade: 0
R15 = CMP-0023073-5: RES, 39.0 k, 1%, 0.1 W, 0603; Manufacturer: Yageo; Power_W: 100mW; TempCo: 100 ppm/C; Value_Code: 39k0; Value: 39.0k; Res_ohm: 39k; SizeX_mm: 1.6; SizeY_mm: 0.8; SizeZ_mm: 1; Value2: 0.1W; SizeArea_mm2: 1.28; AEC Qualified: N; VDC_V: 75V; AEC Category: Q200; SizeAreaWB_mm2: 4.68
R16 R37 R53 = CMP-0022237-4: RES, 24.9 k, 1%, 0.1 W, AEC-Q200 Grade 0, 0603; Manufacturer: Vishay-Dale; Power_W: 100mW; TempCo: 100 ppm/C; Value_Code: 24k9; Value: 24.9k; EIA_Code: E96; SizeX_mm: 1.6; SizeY_mm: 0.8; SizeZ_mm: 1; Value2: 0.1W; SizeArea_mm2: 1.28; AEC Qualified: Y; VDC_V: 75V; AEC Category: Q200; AEC Grade: 0
R17 = CMP-0022330-4: RES, 31.6 k, 1%, 0.1 W, AEC-Q200 Grade 0, 0603; Manufacturer: Vishay-Dale; Power_W: 100mW; TempCo: 100 ppm/C; Value_Code: 31k6; Value: 31.6k; EIA_Code: E96; SizeX_mm: 1.6; SizeY_mm: 0.8; SizeZ_mm: 1; Value2: 0.1W; SizeArea_mm2: 1.28; AEC Qualified: Y; VDC_V: 75V; AEC Category: Q200; AEC Grade: 0
R19 = CMP-0022443-4: RES, 48.7 k, 1%, 0.1 W, AEC-Q200 Grade 0, 0603; Manufacturer: Vishay-Dale; Power_W: 100mW; TempCo: 100 ppm/C; Value_Code: 48k7; Value: 48.7k; EIA_Code: E96; SizeX_mm: 1.6; SizeY_mm: 0.8; SizeZ_mm: 1; Value2: 0.1W; SizeArea_mm2: 1.28; AEC Qualified: Y; VDC_V: 75V; AEC Category: Q200; AEC Grade: 0
R20 = CMP-0022536-4: RES, 61.9 k, 1%, 0.1 W, AEC-Q200 Grade 0, 0603; Manufacturer: Vishay-Dale; Power_W: 100mW; TempCo: 100 ppm/C; Value_Code: 61k9; Value: 61.9k; EIA_Code: E96; SizeX_mm: 1.6; SizeY_mm: 0.8; SizeZ_mm: 1; Value2: 0.1W; SizeArea_mm2: 1.28; AEC Qualified: Y; VDC_V: 75V; AEC Category: Q200; AEC Grade: 0
R22 = CMP-0022651-4: RES, 90.9 k, 1%, 0.1 W, AEC-Q200 Grade 0, 0603; Manufacturer: Vishay-Dale; Power_W: 100mW; TempCo: 100 ppm/C; Value_Code: 90k9; Value: 90.9k; EIA_Code: E96; SizeY_mm: 0.8; SizeZ_mm: 1; Value2: 0.1W; SizeArea_mm2: 1.28; SizeX_mm: 1.6; AEC Qualified: Y; VDC_V: 75V; AEC Category: Q200; AEC Grade: 0
R23 = CMP-0022008-4: RES, 110 k, 1%, 0.1 W, AEC-Q200 Grade 0, 0603; Manufacturer: Vishay-Dale; Power_W: 100mW; TempCo: 100 ppm/C; Value: 110k; EIA_Code: E96; SizeX_mm: 1.6; SizeY_mm: 0.8; SizeZ_mm: 1; Value2: 0.1W; SizeArea_mm2: 1.28; AEC Qualified: Y; VDC_V: 75V; AEC Category: Q200; AEC Grade: 0
R25 R41 = CMP-0022481-5: RES, 511, 1%, 0.1 W, AEC-Q200 Grade 0, 0603; Manufacturer: Vishay-Dale; Power_W: 100mW; TempCo: 100 ppm/C; Value_Code: 511R; Value: 511; EIA_Code: E96; SizeX_mm: 1.6; SizeY_mm: 0.8; SizeZ_mm: 1; Value2: 0.1W; SizeArea_mm2: 1.28; AEC Qualified: Y; VDC_V: 75V; AEC Category: Q200; AEC Grade: 0
R26 R42 = CMP-0022120-4: RES, 1.30 k, 1%, 0.1 W, AEC-Q200 Grade 0, 0603; Manufacturer: Vishay-Dale; Power_W: 100mW; TempCo: 100 ppm/C; Value_Code: 1k30; Value: 1.30k; EIA_Code: E96; Res_ohm: 1.3k; SizeX_mm: 1.6; SizeY_mm: 0.8; SizeZ_mm: 1; Value2: 0.1W; SizeArea_mm2: 1.28; AEC Qualified: Y; VDC_V: 75V; AEC Category: Q200; AEC Grade: 0
R27 R43 = CMP-0022135-4: RES, 1.87 k, 1%, 0.1 W, AEC-Q200 Grade 0, 0603; Manufacturer: Vishay-Dale; Power_W: 100mW; TempCo: 100 ppm/C; Value_Code: 1k87; Value: 1.87k; EIA_Code: E96; SizeX_mm: 1.6; SizeY_mm: 0.8; SizeZ_mm: 1; Value2: 0.1W; SizeArea_mm2: 1.28; AEC Qualified: Y; VDC_V: 75V; AEC Category: Q200; AEC Grade: 0
R28 R44 = CMP-0022281-4: RES, 2.74 k, 1%, 0.1 W, AEC-Q200 Grade 0, 0603; Manufacturer: Vishay-Dale; Power_W: 100mW; TempCo: 100 ppm/C; Value_Code: 2k74; Value: 2.74k; EIA_Code: E96; SizeX_mm: 1.6; SizeY_mm: 0.8; SizeZ_mm: 1; Value2: 0.1W; SizeArea_mm2: 1.28; AEC Qualified: Y; VDC_V: 75V; AEC Category: Q200; AEC Grade: 0
R29 R45 = CMP-0022381-4: RES, 3.83 k, 1%, 0.1 W, AEC-Q200 Grade 0, 0603; Manufacturer: Vishay-Dale; Power_W: 100mW; TempCo: 100 ppm/C; Value_Code: 3k83; Value: 3.83k; EIA_Code: E96; SizeX_mm: 1.6; SizeY_mm: 0.8; SizeZ_mm: 1; Value2: 0.1W; SizeArea_mm2: 1.28; AEC Qualified: Y; VDC_V: 75V; AEC Category: Q200; AEC Grade: 0
R30 R46 = CMP-0022509-4: RES, 5.11 k, 1%, 0.1 W, AEC-Q200 Grade 0, 0603; Manufacturer: Vishay-Dale; Power_W: 100mW; TempCo: 100 ppm/C; Value_Code: 5k11; Value: 5.11k; EIA_Code: E96; SizeX_mm: 1.6; SizeY_mm: 0.8; SizeZ_mm: 1; Value2: 0.1W; SizeArea_mm2: 1.28; AEC Qualified: Y; VDC_V: 75V; AEC Category: Q200; AEC Grade: 0
R31 R47 = CMP-0022561-4: RES, 6.49 k, 1%, 0.1 W, AEC-Q200 Grade 0, 0603; Manufacturer: Vishay-Dale; Power_W: 100mW; TempCo: 100 ppm/C; Value_Code: 6k49; Value: 6.49k; EIA_Code: E96; SizeX_mm: 1.6; SizeY_mm: 0.8; SizeZ_mm: 1; Value2: 0.1W; SizeArea_mm2: 1.28; AEC Qualified: Y; VDC_V: 75V; AEC Category: Q200; AEC Grade: 0
R32 R48 = CMP-0022635-4: RES, 8.25 k, 1%, 0.1 W, AEC-Q200 Grade 0, 0603; Manufacturer: Vishay-Dale; Power_W: 100mW; TempCo: 100 ppm/C; Value_Code: 8k25; Value: 8.25k; EIA_Code: E96; SizeX_mm: 1.6; SizeY_mm: 0.8; SizeZ_mm: 1; Value2: 0.1W; SizeArea_mm2: 1.28; AEC Qualified: Y; VDC_V: 75V; AEC Category: Q200; AEC Grade: 0
R33 R49 = CMP-0022000-4: RES, 10.5 k, 1%, 0.1 W, AEC-Q200 Grade 0, 0603; Manufacturer: Vishay-Dale; Power_W: 100mW; TempCo: 100 ppm/C; Value_Code: 10k5; Value: 10.5k; EIA_Code: E96; SizeX_mm: 1.6; SizeY_mm: 0.8; SizeZ_mm: 1; Value2: 0.1W; SizeArea_mm2: 1.28; AEC Qualified: Y; VDC_V: 75V; AEC Category: Q200; AEC Grade: 0
R34 R50 = CMP-0022043-4: RES, 13.3 k, 1%, 0.1 W, AEC-Q200 Grade 0, 0603; Manufacturer: Vishay-Dale; Power_W: 100mW; TempCo: 100 ppm/C; Value_Code: 13k3; Value: 13.3k; EIA_Code: E96; SizeX_mm: 1.6; SizeY_mm: 0.8; SizeZ_mm: 1; Value2: 0.1W; SizeArea_mm2: 1.28; AEC Qualified: Y; VDC_V: 75V; AEC Category: Q200; AEC Grade: 0
R35 R51 = CMP-0022079-4: RES, 16.2 k, 1%, 0.1 W, AEC-Q200 Grade 0, 0603; Manufacturer: Vishay-Dale; Power_W: 100mW; TempCo: 100 ppm/C; Value_Code: 16k2; Value: 16.2k; EIA_Code: E96; SizeX_mm: 1.6; SizeY_mm: 0.8; SizeZ_mm: 1; Value2: 0.1W; SizeArea_mm2: 1.28; AEC Qualified: Y; VDC_V: 75V; AEC Category: Q200; AEC Grade: 0
R36 R52 = CMP-0022205-4: RES, 20.5 k, 1%, 0.1 W, AEC-Q200 Grade 0, 0603; Manufacturer: Vishay-Dale; Power_W: 100mW; TempCo: 100 ppm/C; Value_Code: 20k5; Value: 20.5k; EIA_Code: E96; SizeX_mm: 1.6; SizeY_mm: 0.8; SizeZ_mm: 1; Value2: 0.1W; SizeArea_mm2: 1.28; AEC Qualified: Y; VDC_V: 75V; AEC Category: Q200; AEC Grade: 0
R38 R54 = CMP-0022324-4: RES, 30.1 k, 1%, 0.1 W, AEC-Q200 Grade 0, 0603; Manufacturer: Vishay-Dale; Power_W: 100mW; TempCo: 100 ppm/C; Value_Code: 30k1; Value: 30.1k; EIA_Code: E96; SizeX_mm: 1.6; SizeY_mm: 0.8; SizeZ_mm: 1; Value2: 0.1W; SizeArea_mm2: 1.28; AEC Qualified: Y; VDC_V: 75V; AEC Category: Q200; AEC Grade: 0
R39 R55 = CMP-0022356-4: RES, 36.5 k, 1%, 0.1 W, AEC-Q200 Grade 0, 0603; Manufacturer: Vishay-Dale; Power_W: 100mW; TempCo: 100 ppm/C; Value_Code: 36k5; Value: 36.5k; EIA_Code: E96; SizeX_mm: 1.6; SizeY_mm: 0.8; SizeZ_mm: 1; Value2: 0.1W; SizeArea_mm2: 1.28; AEC Qualified: Y; VDC_V: 75V; AEC Category: Q200; AEC Grade: 0
R60 = CMP-0022490-4: RES, 53.6 k, 1%, 0.1 W, AEC-Q200 Grade 0, 0603; Manufacturer: Vishay-Dale; Power_W: 100mW; TempCo: 100 ppm/C; Value_Code: 53k6; Value: 53.6k; EIA_Code: E96; SizeX_mm: 1.6; SizeY_mm: 0.8; SizeZ_mm: 1; Value2: 0.1W; SizeArea_mm2: 1.28; AEC Qualified: Y; VDC_V: 75V; AEC Category: Q200; AEC Grade: 0
R65 = CMP-0022548-4: RES, 66.5 k, 1%, 0.1 W, AEC-Q200 Grade 0, 0603; Manufacturer: Vishay-Dale; Power_W: 100mW; TempCo: 100 ppm/C; Value_Code: 66k5; Value: 66.5k; EIA_Code: E96; SizeX_mm: 1.6; SizeY_mm: 0.8; SizeZ_mm: 1; Value2: 0.1W; SizeArea_mm2: 1.28; AEC Qualified: Y; VDC_V: 75V; AEC Category: Q200; AEC Grade: 0
S1-S5 = CMP-0002229-1: Switch, SPST, 8 Pos, 25mA, 24VDC, SMD; Manufacturer: CTS Electrocomponents; CurrentRating_mA: 25A; PositionCount: 8; VDC_V: 24V; SwitchFunction: Off-On
T1-T4 = CMP-0075010-2: Terminal 70A Lug; Manufacturer: Panduit; CompType: Screw Terminal; CT: False; Green_Lifecycle: Not Set; Green_REACh: Incomplete
TP1 = CMP-0067620-1: PC Test Point, SMT; Manufacturer: TE Connectivity
U1 = CMP-0125772-1: 2.5MHz 42V wide-VIN synchronous GaN boost converter with output voltage tracking 22-VQFN-FCRLF -40 to 125; Manufacturer: Texas Instruments; SizeZ_mm: 0.85mm; AEC Qualified: No; Max Duty Cycle: 99%; Min Supply Voltage: 2.5V; Number Of Outputs: 1; Output Type: AdjustableProgrammable; Output Voltage: 6-60V; Standoff Height: 0mm; Switching Frequency: 300-2500kHz; TJmax_C: +150°C

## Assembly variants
001: not fitted C7 C20 C52 C53 C54 C55 FID1 FID2 FID3 J25 J26 J27 JP8 R3 R4 R10 TP1
002: not fitted C7 C20 C52 C53 C54 C55 FID1 FID2 FID3 J25 J26 J27 JP8 R3 R4 R10 TP1; alternate parts U1 -> CMP-0126469-1
003: not fitted C7 C20 C52 C53 C54 C55 FID1 FID2 FID3 J25 J26 J27 JP8 R3 R4 R10 TP1; alternate parts U1 -> CMP-0126470-1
